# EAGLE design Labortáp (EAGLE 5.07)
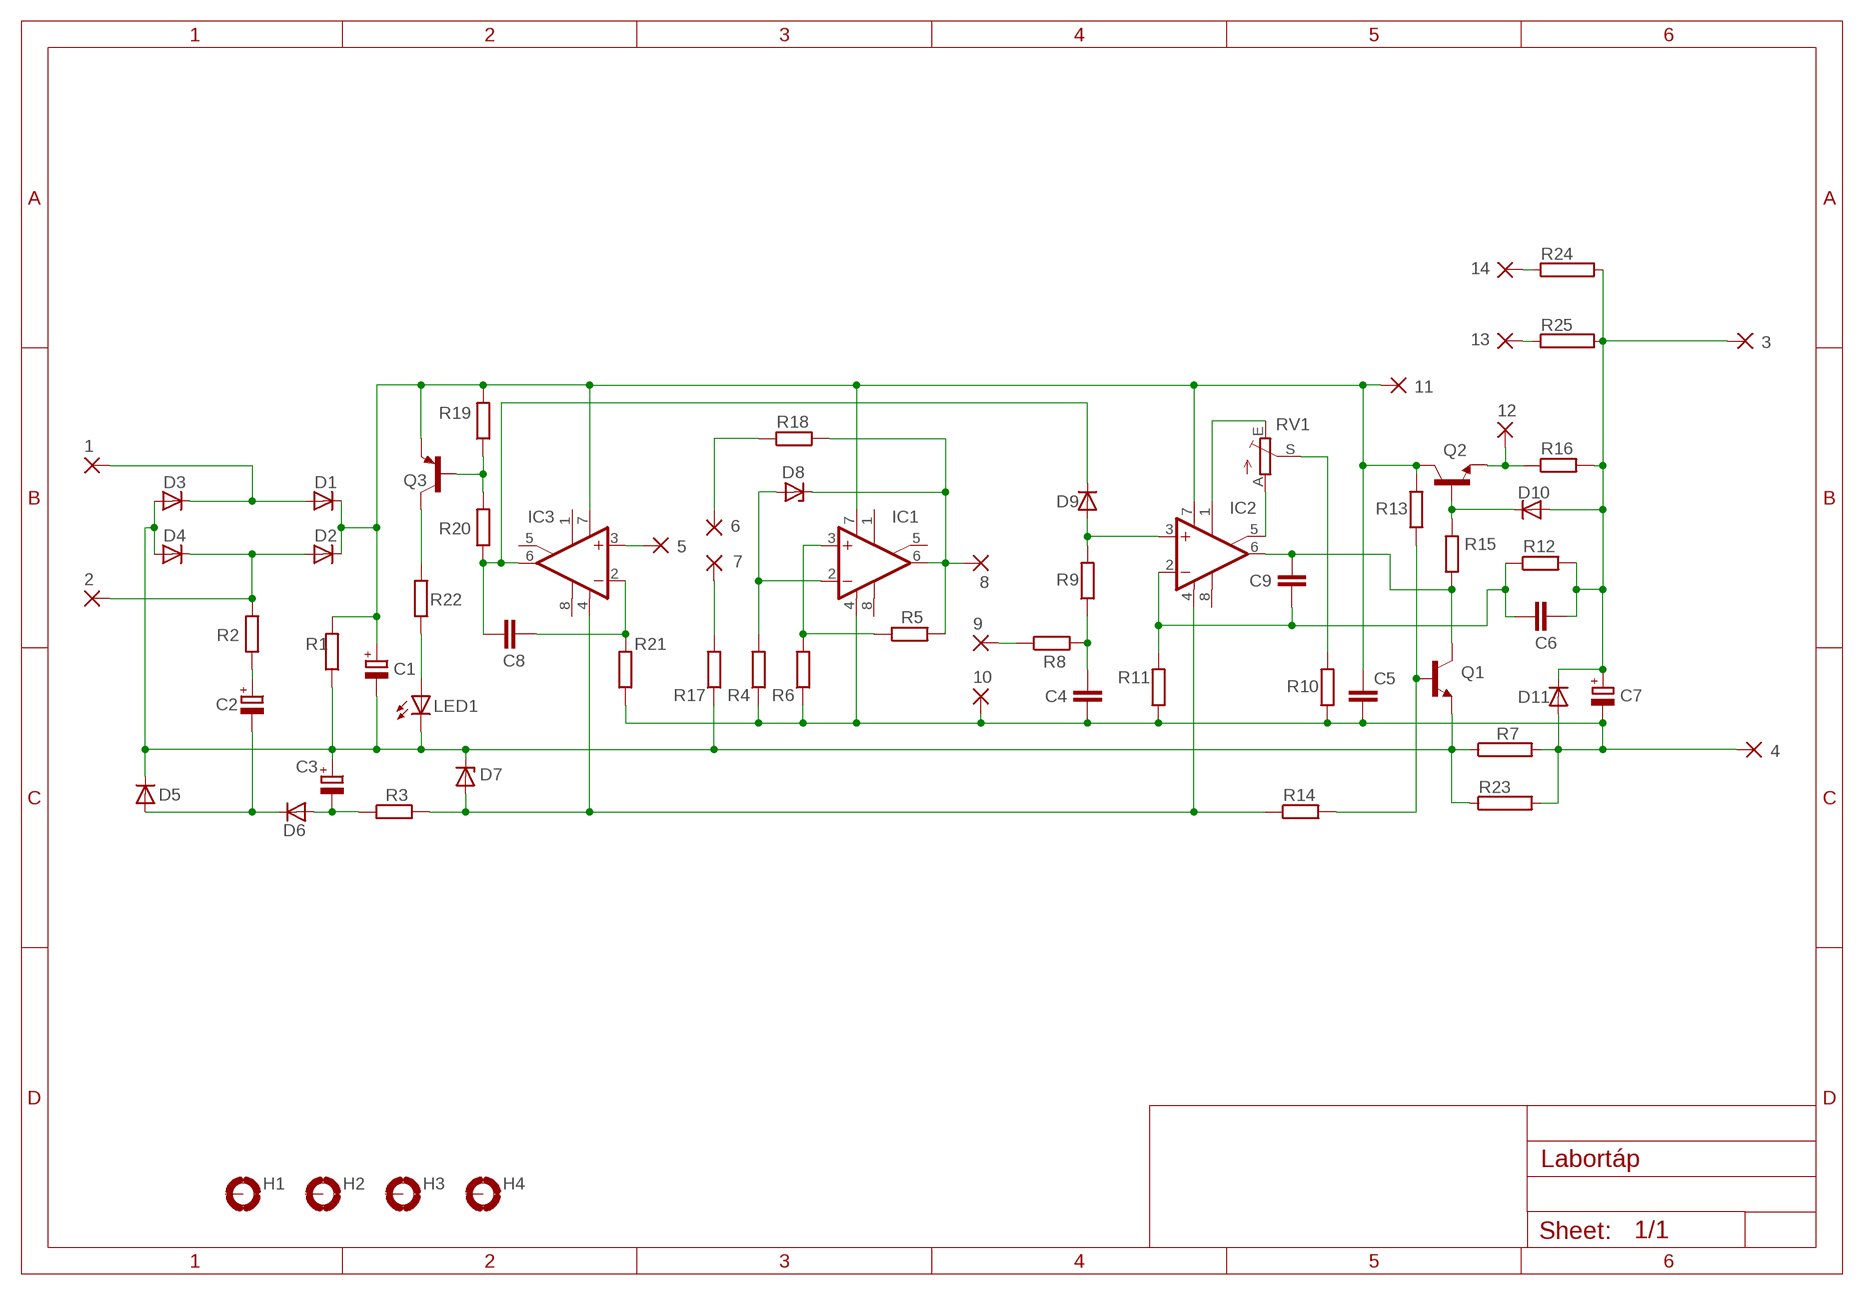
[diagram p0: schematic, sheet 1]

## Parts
1  3,81/1,4  [3,81/1,4]
2  3,81/1,4  [3,81/1,4]
3  3,81/1,4  [3,81/1,4]
4  3,81/1,4  [3,81/1,4]
5  2,15/1,0  [2,15/1,0]
6  2,15/1,0  [2,15/1,0]
7  2,15/1,0  [2,15/1,0]
8  2,15/1,0  [2,15/1,0]
9  2,15/1,0  [2,15/1,0]
10  2,15/1,0  [2,15/1,0]
11  3,17/1,1  [3,17/1,1]
12  3,17/1,1  [3,17/1,1]
13  3,17/1,1  [3,17/1,1]
14  3,17/1,1  [3,17/1,1]
C1  CPOL-EUE7.5-16  [E7,5-16]
C2  CPOL-EUE5-6  [E5-6]
C3  CPOL-EUE5-6  [E5-6]
C4  C-EU050-025X075  [C050-025X075]
C5  C-EU050-025X075  [C050-025X075]
C6  C-EU050-024X044  [C050-024X044]
C7  CPOL-EUE2-5  [E2-5]
C8  C-EU050-024X044  [C050-024X044]
C9  C-EU050-024X044  [C050-024X044]
D1  1N5400  [DO201-15]
D2  1N5400  [DO201-15]
D3  1N5400  [DO201-15]
D4  1N5400  [DO201-15]
D5  1N4148DO35-10  [DO35-10]
D6  1N4148DO35-10  [DO35-10]
D7  ZENER-DIODEDO35Z10  [DO35Z10]
D8  ZENER-DIODEDO35Z10  [DO35Z10]
D9  1N4148DO35-10  [DO35-10]
D10  1N4148DO35-10  [DO35-10]
D11  1N4004  [DO41-10]
H1  MOUNT-PAD-ROUND3.0  [3,0-PAD]
H2  MOUNT-PAD-ROUND3.0  [3,0-PAD]
H3  MOUNT-PAD-ROUND3.0  [3,0-PAD]
H4  MOUNT-PAD-ROUND3.0  [3,0-PAD]
IC1  TL081P  [DIL08]
IC2  TL081P  [DIL08]
IC3  TL081P  [DIL08]
LED1  LED5MM  [LED5MM]
Q1  BC547  [TO92]
Q2  BC141-10  [TO39]
Q3  BC557  [TO92]
R1  R-EU_0309/10  [0309/10]
R2  R-EU_0207/10  [0207/10]
R3  R-EU_0207/10  [0207/10]
R4  R-EU_0207/10  [0207/10]
R5  R-EU_0207/10  [0207/10]
R6  R-EU_0207/10  [0207/10]
R7  RKH208-8  [KH208-8]
R8  R-EU_0207/10  [0207/10]
R9  R-EU_0207/10  [0207/10]
R10  R-EU_0207/10  [0207/10]
R11  R-EU_0207/10  [0207/10]
R12  R-EU_0207/10  [0207/10]
R13  R-EU_0207/10  [0207/10]
R14  R-EU_0207/10  [0207/10]
R15  R-EU_0207/10  [0207/10]
R16  R-EU_0207/10  [0207/10]
R17  R-EU_0207/10  [0207/10]
R18  R-EU_0207/10  [0207/10]
R19  R-EU_0207/10  [0207/10]
R20  R-EU_0207/10  [0207/10]
R21  R-EU_0207/10  [0207/10]
R22  R-EU_0207/10  [0207/10]
R23  RKH208-8  [KH208-8]
R24  RKH208-8  [KH208-8]
R25  RKH208-8  [KH208-8]
RV1  TRIM_EU-S64Y  [S64Y]

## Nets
N$1: 1.1(P) D1.A D3.C
N$2: 2.1(P) D2.A D4.C R2.2
N$4: C1.- C3.+ D3.A D4.A D5.C D7.C LED1.K(C) Q1.1(E) R1.1 R7.1 R17.1 R23.1
N$5: C2.+ R2.1
N$6: C8.2 D9.C IC3.6(OUT) R20.1
N$7: C2.- D5.A D6.C
N$8: C3.- D6.A R3.1
N$9: D7.A IC2.4(V-) IC3.4(V-) R3.2 R14.1
N$10: C8.1 IC3.2(-IN) R21.2
N$11: 5.1(P) IC3.3(+IN)
N$12: Q3.2(B) R19.1 R20.2
N$13: Q3.3(C) R22.2
N$14: LED1.A R22.1
N$15: 7.1(P) R17.2
N$16: 4.1(P) 10.1(P) C4.2 C5.2 C7.- D11.A IC1.4(V-) R4.1 R6.1 R7.2 R10.1 R11.1 R21.1 R23.2
N$17: D8.A IC1.2(-IN) R4.2
N$18: IC1.3(+IN) R5.1 R6.2
N$19: 8.1(P) D8.C IC1.6(OUT) R5.2 R18.2
N$20: 6.1(P) R18.1
N$21: 9.1(P) R8.1
N$22: C4.1 R8.2 R9.1
N$23: D9.A IC2.3(+IN) R9.2
N$24: C9.1 IC2.6(OUT) Q1.3(C) R15.1
N$25: IC2.1(ON1) RV1.E
N$26: R10.2 RV1.S
N$27: C6.1 C9.2 IC2.2(-IN) R11.2 R12.1
N$28: Q1.2(B) R13.1 R14.2
N$30: 11.1(P) C1.+ C5.1 D1.C D2.C IC1.7(V+) IC2.7(V+) IC3.7(V+) Q2.3(C) Q3.1(E) R1.2 R13.2 R19.2
N$31: D10.C Q2.2(B) R15.2
N$32: 3.1(P) C6.2 C7.+ D10.A D11.C R12.2 R16.2 R24.2 R25.2
N$34: IC2.5(ON2) RV1.A
N$35: 13.1(P) R25.1
N$36: 12.1(P) Q2.1(E) R16.1
N$37: 14.1(P) R24.1
Unconnected: H1.B3,0(MOUNT) H2.B3,0(MOUNT) H3.B3,0(MOUNT) H4.B3,0(MOUNT) IC1.1(ON1) IC1.5(ON2) IC1.8(OPT) IC2.8(OPT) IC3.1(ON1) IC3.5(ON2) IC3.8(OPT)

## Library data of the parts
1-4 = wirepad:3,81/1,4: THROUGH-HOLE PAD
5-10 = wirepad:2,15/1,0: THROUGH-HOLE PAD
11-14 = wirepad:3,17/1,1: THROUGH-HOLE PAD
C1-C3 C7 = rcl:CPOL-EU: POLARIZED CAPACITOR, European symbol
C4-C6 C8 C9 = rcl:C-EU: CAPACITOR, European symbol
D1-D4 = diode:1N5400: DIODE
D5 D6 D9 D10 = diode:1N4148: DIODE
D7 D8 = diode:ZENER-DIODE: Z-Diode
D11 = diode:1N4004: DIODE
H1-H4 = holes:MOUNT-PAD-ROUND: MOUNTING PAD, round
IC1-IC3 = linear:TL081: OP AMP
LED1 = led:LED: LED
Q1 = transistor-neu-to92:BC547: NPN TRANSISTOR
Q2 = transistor-npn:BC141-10: NPN Transistor
Q3 = transistor-pnp:BC557: PNP Transistor
R1-R6 R8-R22 = rcl:R-EU_: RESISTOR, European symbol
R7 R23-R25 = resistor-power:R: Power Resitor
RV1 = pot:TRIM_EU-: POTENTIOMETER

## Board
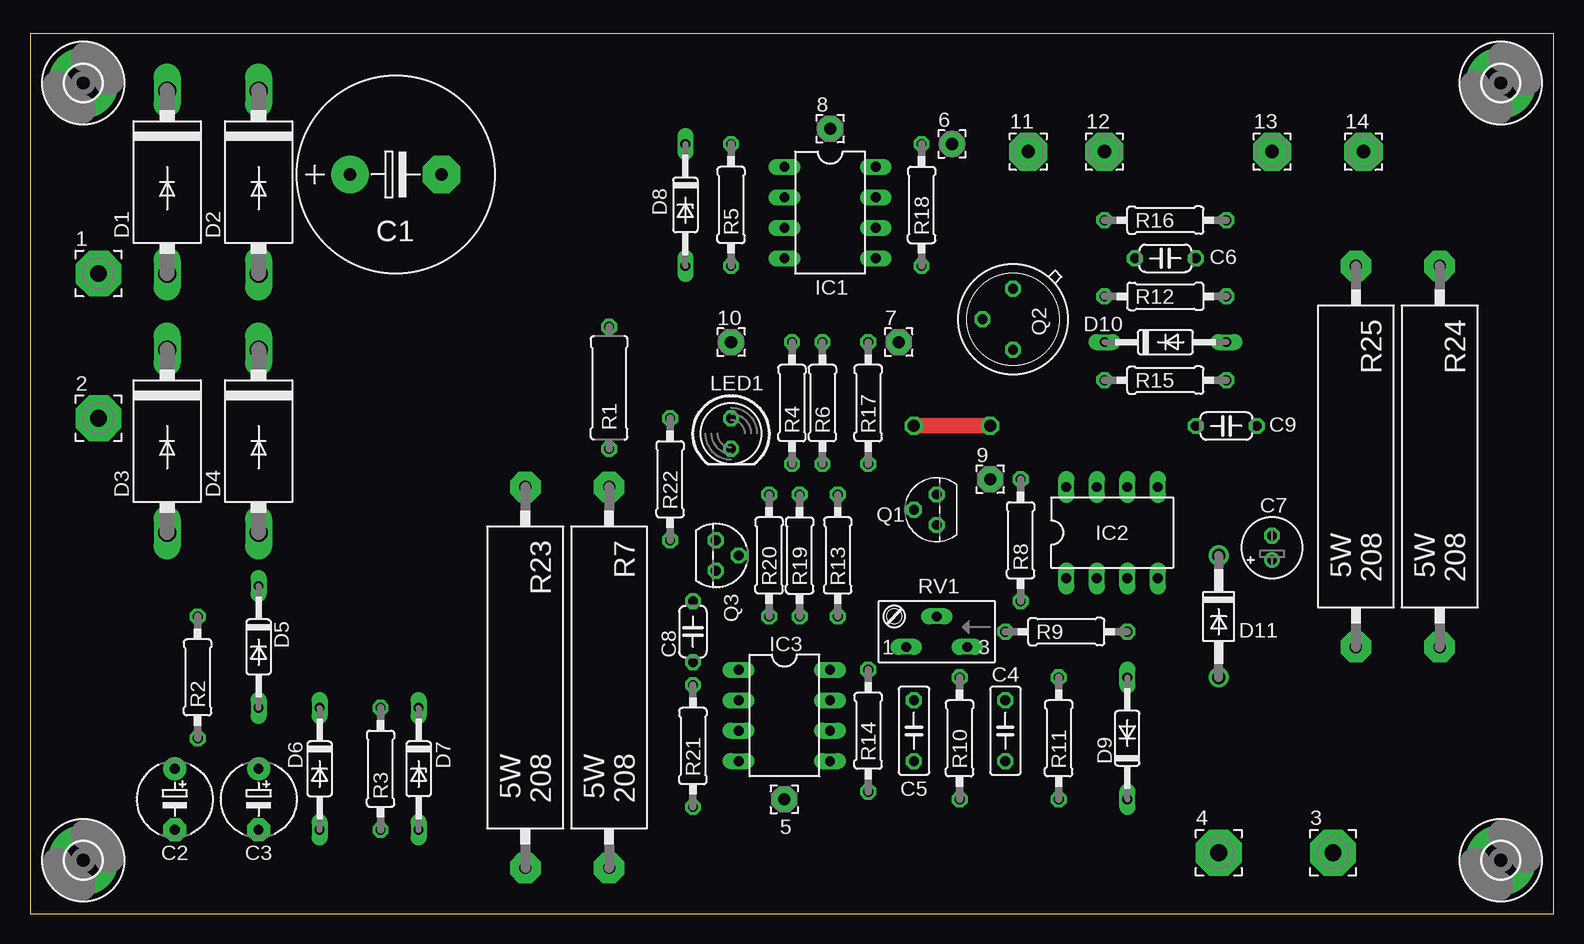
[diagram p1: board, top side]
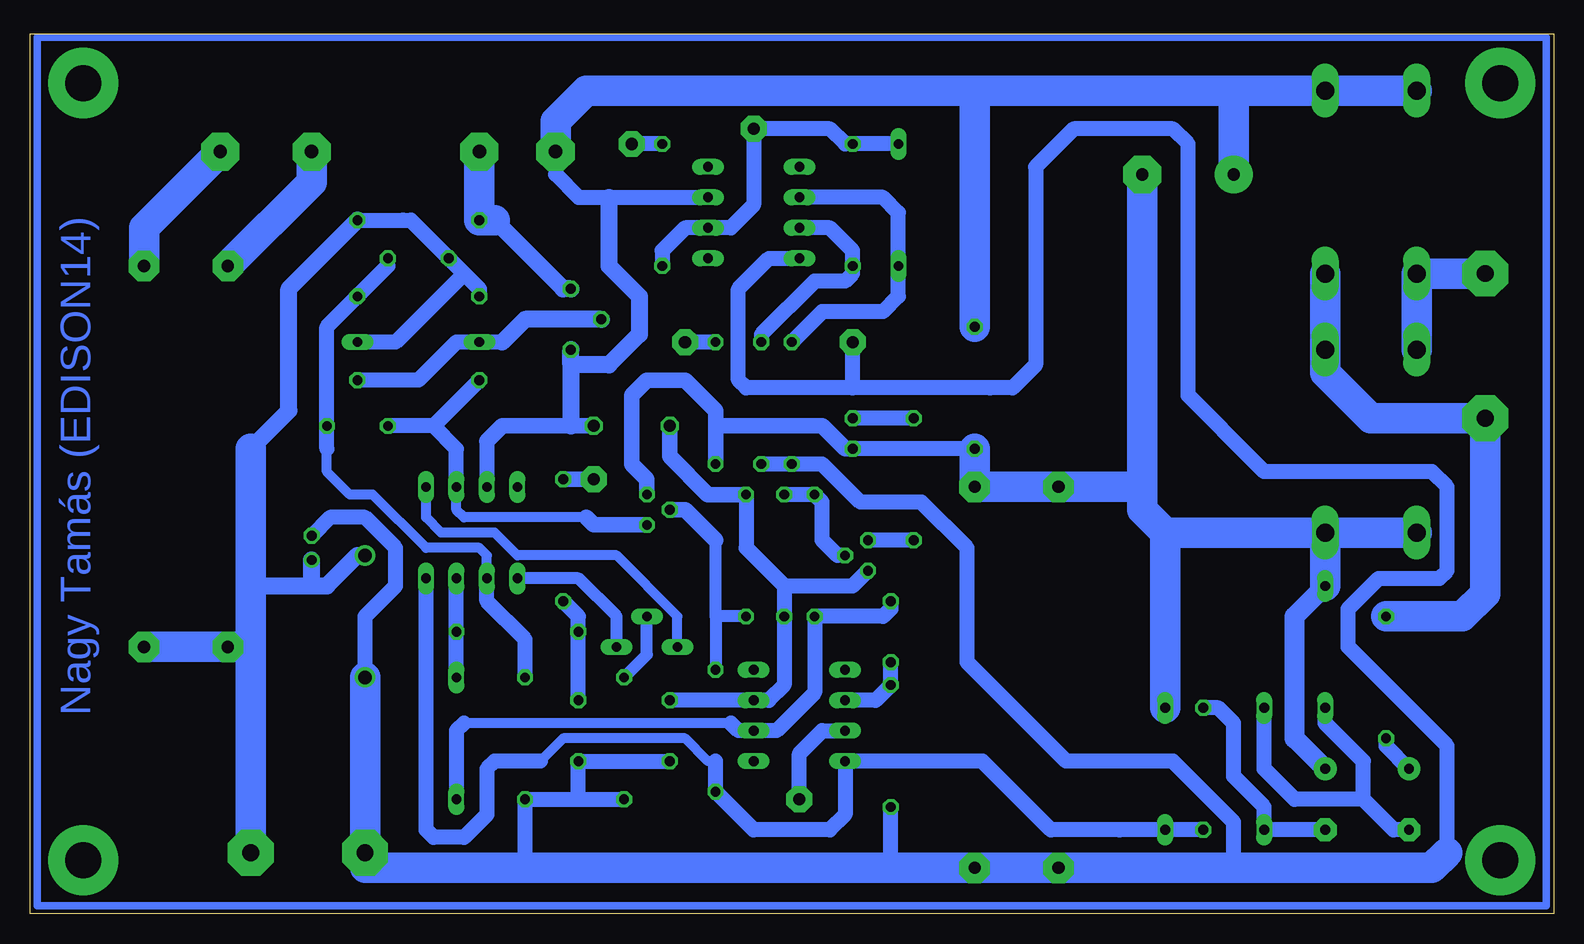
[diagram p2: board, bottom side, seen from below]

Size 126.98 x 73.33 mm. Coordinates in mm from the lower left corner, seen from the top.
Outline: 0,0 126.98,0 126.98,73.33 0,73.33 0,0
Copper layers (1*16): Top 0.035mm / dielectric 1.5mm / Bottom 0.035mm
Design rules "default *": minimum track width 10mil, minimum drill 24mil, track to track 8mil, track to pad 8mil, pad to pad 8mil, via to via 8mil, smd to smd 8mil, copper to edge 40mil, drill to drill 8mil, minimum pad ring 10mil, minimum via ring 8mil, stop-mask expansion 4mil, vias tented up to drill 0mil, thermal gap 10mil

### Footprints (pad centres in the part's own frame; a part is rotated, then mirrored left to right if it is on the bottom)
3,81/1,4 = drill 1.397 pad 3.81 octagon: 1 0,0
2,15/1,0 = drill 1.016 pad 2.159 octagon: 1 0,0
3,17/1,1 = drill 1.118 pad 3.175 octagon: 1 0,0
E7,5-16 = drill 1.016 pad 3.15 round: + -3.81,0 | drill 1.016 pad 3.15 octagon: - 3.81,0
E5-6 = drill 0.813 pad 1.905 round: + -2.54,0 | drill 0.813 pad 1.905 octagon: - 2.54,0
C050-025X075 = drill 0.813 octagon: 1 -2.54,0; 2 2.54,0
C050-024X044 = drill 0.813 octagon: 1 -2.54,0; 2 2.54,0
E2-5 = drill 0.813 pad 1.27 round: + -1.016,0 | drill 0.813 pad 1.27 octagon: - 1.016,0
DO201-15 = drill 1.499 long: A 7.62,0; C -7.62,0
DO35-10 = drill 0.813 long: A 5.08,0; C -5.08,0
DO35Z10 = drill 0.813 long: A 5.08,0; C -5.08,0
DO41-10 = drill 1.118 round: A 5.08,0; C -5.08,0
3,0-PAD = drill 3 pad 5.842 round: B3,0 0,0
DIL08 = drill 0.813 long: 1 -3.81,-3.81; 2 -1.27,-3.81; 3 1.27,-3.81; 4 3.81,-3.81; 5 3.81,3.81; 6 1.27,3.81; 7 -1.27,3.81; 8 -3.81,3.81
LED5MM = drill 0.813 octagon: A -1.27,0; K 1.27,0
TO92 = drill 0.813 octagon: 1 1.27,0; 2 0,1.905; 3 -1.27,0
TO39 = drill 0.813 octagon: 1 0,-2.54; 2 2.54,0; 3 0,2.54
0309/10 = drill 0.813 octagon: 1 -5.08,0; 2 5.08,0
0207/10 = drill 0.813 octagon: 1 -5.08,0; 2 5.08,0
KH208-8 = drill 1.016 pad 2.54 octagon: 1 -15.875,0; 2 15.875,0
S64Y = drill 0.813 long: A 2.54,1.27; E -2.54,1.27; S 0,-1.27

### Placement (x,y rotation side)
1  5.71,53.34 0 top
2  5.71,41.27 0 top
3  108.58,5.08 0 top
4  99.06,5.08 0 top
5  62.87,9.53 0 top
6  76.83,64.14 0 top
7  72.39,47.62 0 top
8  66.67,65.41 0 top
9  80.01,36.2 0 top
10  58.42,47.62 0 top
11  83.19,63.5 0 top
12  89.53,63.5 0 top
13  103.5,63.5 0 top
14  111.12,63.5 0 top
C1  30.48,61.59 0 top
C2  12.06,9.53 270 top
C3  19.05,9.53 270 top
C4  81.28,15.24 270 top
C5  73.66,15.24 270 top
C6  94.61,54.61 180 top
C7  103.5,30.48 90 top
C8  55.24,23.5 90 top
C9  99.69,40.64 0 top
D1  11.43,60.96 270 top
D2  19.05,60.96 270 top
D3  11.43,39.37 270 top
D4  19.05,39.37 270 top
D5  19.05,22.23 270 top
D6  24.13,12.06 270 top
D7  32.38,12.06 270 top
D8  54.61,59.05 270 top
D9  91.44,14.61 90 top
D10  94.61,47.62 0 top
D11  99.06,24.77 270 top
H1  122.56,4.45 0 top
H2  122.56,69.22 0 top
H3  4.45,4.45 0 top
H4  4.45,69.22 0 top
IC1  66.67,58.42 270 top
IC2  90.17,31.75 0 top
IC3  62.87,16.51 270 top
LED1  58.42,40.01 270 top
Q1  75.56,33.66 90 top
Q2  81.92,49.53 180 top
Q3  57.15,29.84 270 top
R1  48.26,43.81 90 top
R2  13.97,19.68 90 top
R3  29.21,12.06 270 top
R4  63.5,42.55 90 top
R5  58.42,59.05 90 top
R6  66.04,42.55 90 top
R7  48.26,19.68 270 top
R8  82.55,31.11 270 top
R9  86.36,23.5 0 top
R10  77.47,14.61 90 top
R11  85.72,14.61 90 top
R12  94.61,51.44 180 top
R13  67.31,29.84 90 top
R14  69.85,15.24 90 top
R15  94.61,44.45 0 top
R16  94.61,57.78 0 top
R17  69.85,42.55 90 top
R18  74.3,59.05 270 top
R19  64.14,29.84 270 top
R20  61.59,29.84 90 top
R21  55.24,13.97 90 top
R22  53.34,36.2 270 top
R23  41.27,19.68 270 top
R24  117.47,38.1 270 top
R25  110.49,38.1 270 top
RV1  75.56,23.5 180 top

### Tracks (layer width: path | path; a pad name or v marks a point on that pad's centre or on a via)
N$1
  Bottom 2.54: 1.1 D1.A D3.C
N$2
  Bottom 2.54: D2.A D4.C 19.05,45.09 15.24,41.27 2.1 5.71,26.67 7.62,24.77 R2.2
N$4
  Bottom 1.27: 48.26,39.37 R1.1 LED1.K
  Bottom 1.3: Q1.1 75.56,36.2 76.83,37.47 76.83,43.18 75.56,44.45 72.39,44.45 69.85,41.91 69.85,40.64 | 69.85,40.64 R17.1 | LED1.K 59.05,38.73 60.96,40.64 69.85,40.64
  Bottom 1.676: C3.+ 21.59,14.61 21.59,24.77 D5.C
  Bottom 2.54: D4.A D3.A | D5.C D4.A | R1.1 48.26,38.1 R7.1 R23.1 34.29,35.56 | 34.29,35.56 34.29,33.66 32.38,31.75 | 34.29,35.56 C1.- | D4.A 32.38,31.75 | 32.38,31.75 D7.C
N$5
  Bottom 1.27: R2.1 13.97,13.97 C2.+
N$6
  Bottom 0.813: 68.58,15.88 90.81,15.88
  Bottom 1.27: C8.2 55.24,25.4 55.88,24.77 R20.1 61.59,18.41 64.77,15.24 IC3.6 67.94,15.24 68.58,15.88 | 90.81,15.88 91.44,15.24 D9.C
N$7
  Bottom 1.27: D5.A 19.05,15.88 15.88,12.7 15.88,9.53 | 15.88,9.53 13.34,6.99 C2.- | D6.C 24.13,12.06 21.59,9.53 15.88,9.53
N$8
  Bottom 1.27: C3.- D6.A 24.13,8.89 26.67,11.43 26.67,15.88 27.94,17.14 R3.1
N$9
  Bottom 0.813: 69.85,12.7 70.48,12.7 72.39,14.61 82.55,14.61 84.45,12.7
  Bottom 1.27: R3.2 D7.A 36.2,6.99 41.91,6.99 47.62,12.7 IC3.4 59.05,8.26 60.33,6.99 66.67,6.99 R14.1 69.85,12.7 | 84.45,12.7 88.27,12.7 88.9,12.06 88.9,8.26 90.81,6.35 93.34,6.35 93.98,6.99 IC2.4
N$10
  Bottom 1.27: IC3.2 56.52,17.78 R21.2 C8.1
N$11
  Bottom 1.27: IC3.3 60.96,15.24 62.87,13.34 5.1
N$12
  Bottom 1.27: Q3.2 59.69,29.84 60.96,31.11 60.96,34.29 R20.2 R19.1
N$13
  Bottom 1.27: R22.2 Q3.3
N$14
  Bottom 1.27: R22.1 LED1.A
N$15
  Bottom 1.27: R17.2 7.1
N$16
  Bottom 1.27: R6.1 R4.1 60.96,37.47 57.78,34.29 53.34,34.29 52.7,34.29 48.9,30.48 48.9,20.95 40.64,12.7 31.75,12.7 26.67,7.62 26.67,3.81 | 55.24,3.81 R21.1 | 58.42,43.81 46.99,43.81 45.09,43.81 43.18,45.72 43.18,62.23 40.64,64.77 40.01,65.41 31.75,65.41 30.48,64.14 30.48,43.18 24.77,37.47 24.13,36.83 10.16,36.83 8.89,35.56 8.89,28.57 9.53,27.94 14.61,27.94 17.14,25.4 17.14,22.23 8.89,13.97 8.89,5.08 | 58.42,43.81 67.31,43.81 67.94,44.45 67.94,52.07 65.41,54.61 IC1.4 | 58.42,43.81 10.1 | C5.2 C4.2 81.28,9.53 | 81.28,9.53 R10.1 | 81.28,9.53 R11.1 85.72,3.81 | D11.A 99.06,24.77 96.52,27.3 96.52,30.48 99.06,33.02 101.98,33.02 C7.-
  Bottom 2.54: R23.2 26.67,3.81 10.16,3.81 8.89,5.08 | R23.2 39.37,3.81 | 39.37,3.81 R7.2 55.24,3.81 85.72,3.81 99.06,3.81 4.1 D11.A | R23.2 39.37,3.81
N$17
  Bottom 1.27: R4.2 60.96,50.16 55.88,50.16 54.61,51.44 D8.A 54.61,58.42 55.88,59.69 IC1.2
N$18
  Bottom 1.27: R6.2 66.04,48.26 61.59,52.7 59.05,52.7 58.42,53.34 R5.1 58.42,55.24 60.33,57.15 IC1.3
N$19
  Bottom 1.27: D8.C R5.2 59.05,64.14 60.33,65.41 8.1 66.67,59.05 68.58,57.15 IC1.6 72.39,57.15 74.3,55.24 R18.2
N$20
  Bottom 1.27: R18.1 6.1
N$21
  Bottom 1.3: 9.1 R8.1
N$22
  Bottom 1.27: C4.1 R9.1 81.28,24.77 R8.2
N$23
  Bottom 1.27: D9.A R9.2 IC2.3
N$24
  Bottom 0.813: 80.64,33.02 90.81,33.02 91.44,33.66 IC2.6
  Bottom 1.27: 93.34,40.64 R15.1 | 93.34,40.64 C9.1 | IC2.6 91.44,38.73 93.34,40.64
  Bottom 1.3: Q1.3 80.01,32.38 80.64,33.02
N$25
  Bottom 1.016: RV1.E 78.11,24.77 81.28,27.94 IC2.1
N$26
  Bottom 1.016: RV1.S 75.56,21.59 R10.2
N$27
  Bottom 0.813: 102.23,38.73 102.23,36.83 100.33,34.92 98.42,34.92 93.98,30.48 89.53,30.48 88.9,29.84 IC2.2
  Bottom 1.27: C6.1 97.16,53.98 R12.1 102.23,48.9 C9.2 102.23,38.73 | R11.2 85.72,22.86 88.9,26.04 IC2.2
N$28
  Bottom 1.016: 69.85,24.77 R14.2 | 69.85,24.77 69.85,31.11 | R13.1 69.85,24.77
  Bottom 1.3: 69.85,31.11 72.39,33.66 Q1.2
N$29
  Bottom 0.61: 0.64,0.64 0.64,73.03 126.36,73.03 126.36,0.64 0.64,0.64
N$30  (via drill 1)
  Top 1.3: v80.01,40.64 v73.66,40.64
  Bottom 1.27: Q3.1 58.42,27.3 64.14,27.3 | 64.14,27.3 67.31,30.48 R13.2 | 64.14,27.3 R19.2 64.14,19.05 65.41,17.78 IC3.7 C5.1 | IC1.7 77.47,59.69 78.74,59.69 81.28,59.69 83.19,61.59 11.1 | 88.9,39.37 IC2.7
  Bottom 1.3: R13.2 70.48,34.92 73.66,38.1 v73.66,40.64 | v80.01,40.64 81.92,40.64 83.19,40.64 87.63,40.64 88.9,39.37
  Bottom 1.422: 81.92,45.72 81.92,40.64 | 81.92,45.72 Q2.3 | 78.74,59.69 78.74,53.98 76.2,51.44 76.2,48.26 78.74,45.72 81.92,45.72
  Bottom 2.54: 19.68,68.58 26.67,68.58 | 26.67,68.58 27.3,68.58 48.26,68.58 | 19.68,68.58 D2.C | 48.26,68.58 R1.2 | 48.26,68.58 80.64,68.58 83.19,66.04 11.1 | D1.C 19.68,68.58 | C1.+ 26.67,67.94 26.67,68.58
N$31
  Bottom 1.27: R15.2 94.61,44.45 91.44,47.62 D10.C 87.63,47.62
  Bottom 1.422: Q2.2 85.72,49.53 87.63,47.62
N$32
  Bottom 1.27: R16.2 95.89,57.78 95.25,57.78 C6.2 90.81,53.34 | 90.81,53.34 89.53,52.07 R12.2 | D10.A 96.52,47.62 90.81,53.34
  Bottom 1.422: R16.2 105.41,52.07 105.41,41.91 107.95,39.37 108.58,38.73 | D11.C 99.69,29.84 102.23,27.3 103.5,27.3 | 108.58,27.3 103.5,27.3 | 103.5,27.3 C7.+
  Bottom 2.54: 3.1 108.58,22.23 | 108.58,22.23 108.58,27.3 108.58,38.73 | 108.58,22.23 109.86,22.23 | 109.86,22.23 R25.2 | R24.2 111.12,22.23 109.86,22.23
N$34
  Bottom 0.813: RV1.A 73.03,24.77 78.11,29.84 86.36,29.84 88.27,31.75 92.71,31.75 93.98,33.02 IC2.5
N$35
  Bottom 2.54: 13.1 103.5,60.96 R25.1
N$36
  Bottom 1.422: Q2.1 82.55,52.07 88.27,57.78
  Bottom 2.54: 12.1 R16.1 88.27,57.78
N$37
  Bottom 2.54: 14.1 117.47,57.15 R24.1

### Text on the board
Bottom: Nagy Tamás (EDISON14)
